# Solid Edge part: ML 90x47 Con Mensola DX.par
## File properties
Title: ML 90X47 CON MENSOLA DX
Author: i.fialdini
Template: Iso Part.par
Last saved by: i.fialdini
Revision: 70
Application: Solid Edge
Tipo di contenuto documento: 0
Accuracy: 0.990
Document Number: 3008
Revision: 0
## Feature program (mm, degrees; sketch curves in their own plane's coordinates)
sketch for "unnamed Protrusion 1" plane through (57.4001, 57.4001, 0) normal (0, 0, 1) x-axis (1, 0, 0)
  line (-517.4001, 177.5999) -> (402.5999, 177.5999)
  line (402.5999, 177.5999) -> (402.5999, -292.4001)
  line (402.5999, -292.4001) -> (-517.4001, -292.4001)
  line (-517.4001, -292.4001) -> (-517.4001, 177.5999)
  dimension (linear) = 517.4001
  dimension (linear) = 517.4001
extrude "unnamed Protrusion 1" add finite 135 along -normal
sketch for "ScavoEstrusione_1" plane through (0, 0, 0) normal (0, 0, 1) x-axis (1, 0, 0)
  line (-450, -225) -> (-450, 225)
  line (-450, 225) -> (450, 225)
  line (450, 225) -> (450, -225)
  line (450, -225) -> (-450, -225)
extrude "ScavoEstrusione_1" cut finite 10 along -normal
sketch for "ScavoEstrusione_2" plane through (0, 0, -10) normal (0, 0, 1) x-axis (1, 0, 0)
  line (-340, -225) -> (110, -225)
  line (110, -225) -> (110, 90)
  line (110, 90) -> (-340, 90)
  line (-340, 90) -> (-340, -225)
  dimension (linear) = 110
extrude "ScavoEstrusione_2" cut finite 110 along -normal
fillet "Rotondo_1" radius 150
sketch for "unnamed Protrusion 2" plane through (-115, 0, -85) normal (-1, 0, 0) x-axis (0, -1, 0)
  line (225, 75) -> (50, -35)
extrude "unnamed Protrusion 2" add through
sketch for "ScavoEstrusione_3" plane through (0, 0, -135) normal (0, 0, -1) x-axis (1, 0, 0)
  line (-415, -235) -> (415, -235)
  line (415, -235) -> (415, 185)
  line (415, 185) -> (-415, 185)
  line (-415, 185) -> (-415, -235)
extrude "ScavoEstrusione_3" cut finite 85 along -normal
sketch for "unnamed Cutout 1" plane through (0, 235, -85) normal (0, 1, 0) x-axis (1, 0, 0)
  line (-415, -35) -> (-460, -35)
  arc centre (-320, -45.5882) radius 95.5882 from (-320, 50) to (-415, -35) ccw
  line (320, 50) -> (-320, 50)
  arc centre (320, -45.5882) radius 95.5882 from (320, 50) to (415, -35) cw
  line (460, -35) -> (415, -35)
  dimension (linear) = 320
  dimension (linear) = 320
  dimension (linear) = 320
extrude "unnamed Cutout 1" cut through along -normal
sketch for "unnamed Cutout 2" plane through (0, 26.3331, 26.3331) normal (-1, 0, 0) x-axis (0, -1, 0)
  line (201.3331, -76.3331) -> (91.3331, -161.3331)
  line (201.3331, -76.3331) -> (258.8331, -76.3331)
extrude "unnamed Cutout 2" cut through
sketch for "ScavoEstrusione_6" plane through (0, 235, -67.5) normal (0, 1, 0) x-axis (1, 0, 0)
  line (-320, 67.5) -> (-320, -17.5)
  line (-320, -17.5) -> (-395.7704, -17.5)
extrude "ScavoEstrusione_6" cut finite 20 along -normal
mirror "unnamed Mirror 1" of "ScavoEstrusione_6" about plane through (0, 0, 0) normal (1, 0, 0)
extrude "unnamed Cutout 3" cut finite 20
sketch for "ProtrusioneEstrusa_3" plane through (0, 0, -150) normal (0, 0, -1) x-axis (0, 1, 0)
  line (-85, -320) -> (235, -320)
  line (235, -320) -> (235, 320)
  line (235, 320) -> (-85, 320)
  line (-85, 320) -> (-85, -320)
  dimension (linear) = 235
extrude "ProtrusioneEstrusa_3" add through along -normal  Profile_Plane1_Distance = 100 mm
thinwall "Spessoramento_1"  Thickness = 25 mm
sketch for "unnamed Protrusion 3" plane through (0, -60, -126.2821) normal (0, 1, 0) x-axis (1, 0, 0)
  line (285, -118.7386) -> (285, 23.7179)
  line (295, 23.7179) -> (285, 23.7179)
extrude "unnamed Protrusion 3" add through
sketch for "unnamed Protrusion 4" plane through (-5, -60, -128.804) normal (0, 1, 0) x-axis (1, 0, 0)
  line (-280, -21.196) -> (-280, 21.196)
  line (-280, 21.196) -> (-290, 21.196)
extrude "unnamed Protrusion 4" add through
sketch for "unnamed Protrusion 5" plane through (295, 33.5595, -97.5) normal (-1, 0, 0) x-axis (0, 1, 0)
  line (-83.5595, -66.429) -> (-83.5595, 52.5)
  line (-83.5595, 52.5) -> (-121.0595, 52.5)
extrude "unnamed Protrusion 5" add to key point along +normal
fillet "Rotondo_4" radius 5
fillet "Rotondo_9" radius 20
fillet "Rotondo_10" radius 5
fillet "Rotondo_11" radius 25
sketch for "ProtrusioneEstrusa_8" plane through (-110, 46.6426, -145) normal (0, 0, -1) x-axis (0, 1, 0)
extrude "ProtrusioneEstrusa_8" add finite 35 along +normal
sketch for "ScavoEstrusione_14" plane through (-106.7151, 10.7408, -180) normal (0, 0, -1) x-axis (1, 0, 0)
  circle centre (-8.2849, -14.2592) radius 22.5
extrude "ScavoEstrusione_14" cut finite 770 along -normal
fillet "Rotondo_12" radius 10
fillet "Rotondo_13" radius 10
fillet "Rotondo_14" radius 10
fillet "Rotondo_16" radius 5
sketch for "ScavoEstrusione_15" plane through (0, -4.6174, -10) normal (0, 0, 1) x-axis (0, 1, 0)
  circle centre (167.4427, 115) radius 18
extrude "ScavoEstrusione_15" cut finite 420 along -normal
fillet "Rotondo_17" radius 5
fillet "Rotondo_18" radius 2
fillet "Rotondo_19" radius 10
fillet "Rotondo_20" radius 2
sketch for "ScavoEstrusione_19" plane through (0, 235, -77.5) normal (0, 1, 0) x-axis (1, 0, 0)
  circle centre (-74.6687, 72.5) radius 70.4568
extrude "ScavoEstrusione_19" cut finite 35 along -normal
fillet "unnamed Round 1"
fillet "Rotondo_24" radius 15
fillet "Rotondo_25" radius 5
fillet "Rotondo_26" radius 5
fillet "Rotondo_27" radius 5
sketch for "ProtrusioneEstrusa_14" plane through (-115, 0, 0) normal (1, 0, 0) x-axis (0, 1, 0)
  line (61.4085, -165.9387) -> (143.0563, -165.9387)
  line (143.0563, -35) -> (143.0563, -165.9387)
extrude "ProtrusioneEstrusa_14" add finite 50 symmetric
fillet "Rotondo_29" radius 15
fillet "Rotondo_30" radius 2
sketch for "ScavoEstrusione_23" #1 plane through (0, 235, -77.5) normal (0, 1, 0) x-axis (1, 0, 0)
sketch for "ScavoEstrusione_23" #2 plane through (0, 235, -77.5) normal (0, 1, 0) x-axis (1, 0, 0)
extrude "ScavoEstrusione_23" cut finite 35 along -normal
fillet "Rotondo_32" radius 2
fillet "Rotondo_34" radius 5
fillet "Rotondo_36" radius 5
fillet "Rotondo_37" radius 5
fillet "Rotondo_40" radius 5
fillet "Rotondo_41" radius 5
fillet "Rotondo_42" radius 5
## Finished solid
Body 1: solid body, 240 faces, 532 edges, 292 vertices.
  Faces by surface: cylinder 101, blend 46, torus 43, plane 34, sphere 16
  Edges by curve: circle 245, line 189, intersection 54, ellipse 44
Bounding box of the edges (mm; curved faces can reach further): 920.000 x 470.000 x 180.000, from (-460, -235, -180) to (460, 235, 0).
Cylindrical faces by radius (mm): R2 x10, R5 x51, R7.5 x4, R10 x13, R15 x5, R18 x1, R20 x4, R22.5 x1, R25 x2, R32.5 x1, R40 x2, R70.4568 x1, R95.5882 x2, R150 x2, R175 x2
Toroidal faces (ring radius, tube radius in mm): R7 r5 x2, R9.5 r2 x8, R10 r5 x5, R12 r2 x4, R20 r5 x4, R23 r5 x2, R24.5 r2 x1, R30.5 r2 x1, R32.5 r10 x1, R35 r5 x4, R37.5 r5 x1, R75.4568 r5 x2, R93.5882 r2 x2, R125 r25 x2, R165 r10 x2, R180 r5 x2
Spherical faces by radius (mm): R5 x16
Planar faces by outward normal: +x 4, +y 8, +z 4, -x 4, -y 4, -z 8, oblique 2
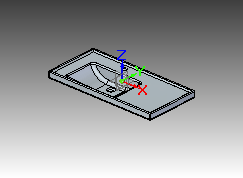
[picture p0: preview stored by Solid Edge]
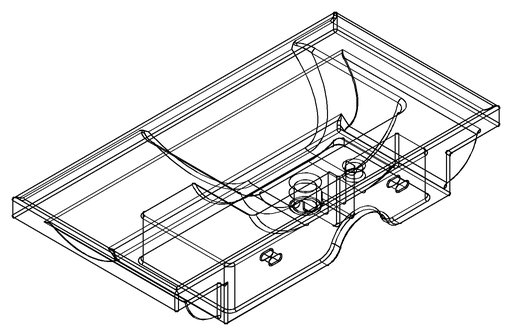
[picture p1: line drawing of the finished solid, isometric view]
